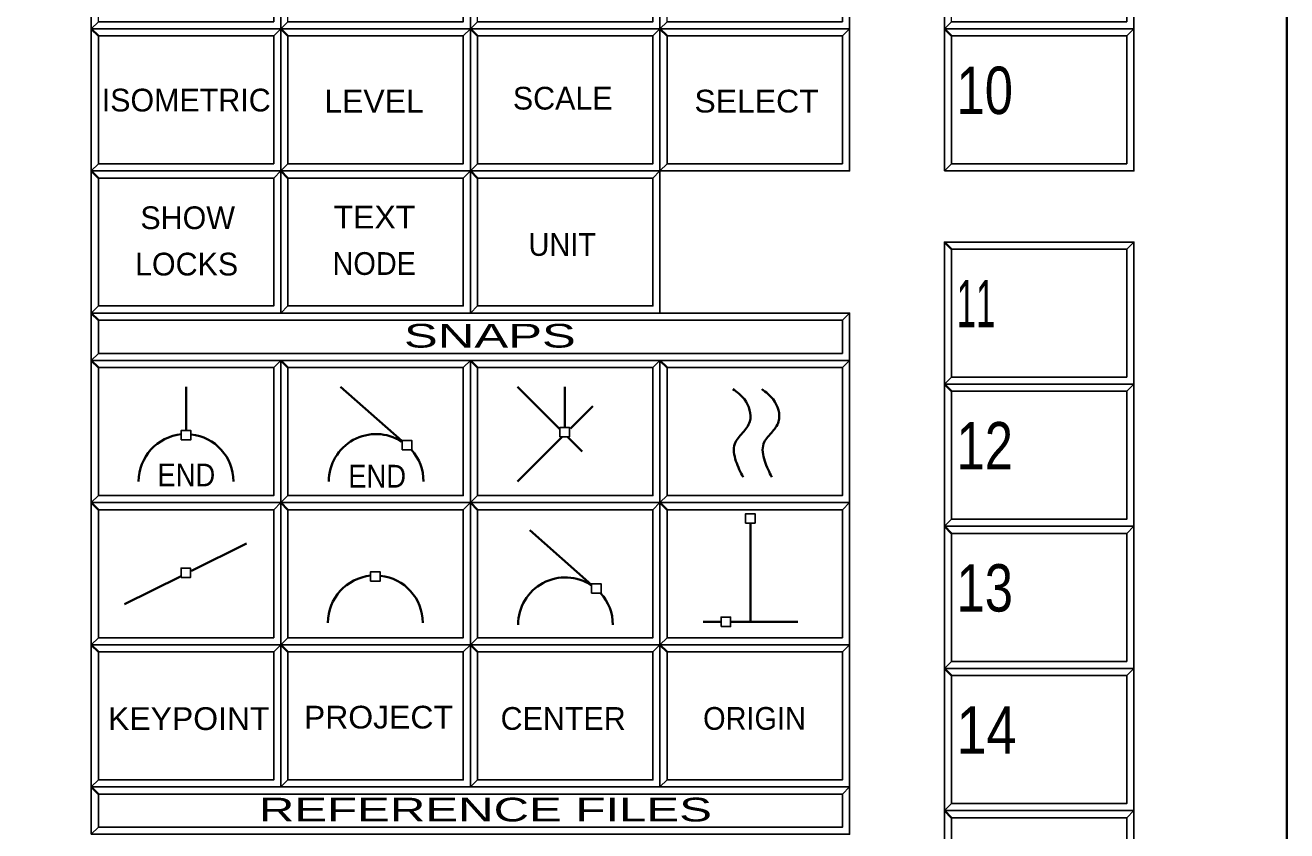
# Model space of a CAD drawing. Extents: x 95906.9 to 95918.9, y 90964.8 to 90972.9.
# Drawn here: x 95916.193 to 95918.855, y 90967.969 to 90969.669 of the extents above; entities that cross this region are included whole.
import ezdxf
from ezdxf.enums import TextEntityAlignment as Align

# ---------------------------------------------------------------- set-up
doc = ezdxf.new("R2010")
doc.units = 0
doc.header["$LTSCALE"] = 0.019
doc.linetypes.add('MEDIUM_DASHED', pattern=[4.5, 3, -1.5])
for name, color, linetype, lineweight in [('1', 7, 'Continuous', 25), ('11', 7, 'Continuous', 25), ('12', 7, 'Continuous', 25), ('2', 7, 'Continuous', 13), ('21', 7, 'Continuous', 25), ('3', 7, 'Continuous', 25), ('4', 7, 'Continuous', 35), ('6', 7, 'Continuous', 35), ('7', 7, 'Continuous', 35)]:
    doc.layers.add(name, color=color, linetype=linetype, lineweight=lineweight)

msp = doc.modelspace()

# ---------------------------------------------------------------- linework, layer by layer
at = {"layer": '1'}
for points in [[(95916.3323, 90969.6617), (95916.7323, 90969.6617), (95916.7323, 90969.9617), (95916.3323, 90969.9617)], [(95916.7323, 90969.6617), (95917.1323, 90969.6617), (95917.1323, 90969.9617), (95916.7323, 90969.9617)], [(95917.1323, 90969.6617), (95917.5323, 90969.6617), (95917.5323, 90969.9617), (95917.1323, 90969.9617)], [(95917.5323, 90969.6617), (95917.9323, 90969.6617), (95917.9323, 90969.9617), (95917.5323, 90969.9617)], [(95918.1323, 90969.6617), (95918.5323, 90969.6617), (95918.5323, 90969.9617), (95918.1323, 90969.9617)], [(95916.3323, 90969.3617), (95916.7323, 90969.3617), (95916.7323, 90969.6617), (95916.3323, 90969.6617)], [(95916.7323, 90969.3617), (95917.1323, 90969.3617), (95917.1323, 90969.6617), (95916.7323, 90969.6617)], [(95917.1323, 90969.3617), (95917.5323, 90969.3617), (95917.5323, 90969.6617), (95917.1323, 90969.6617)], [(95917.5323, 90969.3617), (95917.9323, 90969.3617), (95917.9323, 90969.6617), (95917.5323, 90969.6617)], [(95918.1323, 90969.3617), (95918.5323, 90969.3617), (95918.5323, 90969.6617), (95918.1323, 90969.6617)], [(95916.3323, 90969.0617), (95916.7323, 90969.0617), (95916.7323, 90969.3617), (95916.3323, 90969.3617)], [(95916.7323, 90969.0617), (95917.1323, 90969.0617), (95917.1323, 90969.3617), (95916.7323, 90969.3617)], [(95917.1323, 90969.0617), (95917.5323, 90969.0617), (95917.5323, 90969.3617), (95917.1323, 90969.3617)], [(95918.1323, 90968.9117), (95918.5323, 90968.9117), (95918.5323, 90969.2117), (95918.1323, 90969.2117)], [(95916.3323, 90968.9617), (95917.9323, 90968.9617), (95917.9323, 90969.0617), (95916.3323, 90969.0617)], [(95916.3323, 90968.6617), (95916.7323, 90968.6617), (95916.7323, 90968.9617), (95916.3323, 90968.9617)], [(95916.7323, 90968.6617), (95917.1323, 90968.6617), (95917.1323, 90968.9617), (95916.7323, 90968.9617)], [(95917.1323, 90968.6617), (95917.5323, 90968.6617), (95917.5323, 90968.9617), (95917.1323, 90968.9617)], [(95917.5323, 90968.6617), (95917.9323, 90968.6617), (95917.9323, 90968.9617), (95917.5323, 90968.9617)], [(95918.1323, 90968.6117), (95918.5323, 90968.6117), (95918.5323, 90968.9117), (95918.1323, 90968.9117)], [(95916.3323, 90968.3617), (95916.7323, 90968.3617), (95916.7323, 90968.6617), (95916.3323, 90968.6617)], [(95916.7323, 90968.3617), (95917.1323, 90968.3617), (95917.1323, 90968.6617), (95916.7323, 90968.6617)], [(95917.1323, 90968.3617), (95917.5323, 90968.3617), (95917.5323, 90968.6617), (95917.1323, 90968.6617)], [(95917.5323, 90968.3617), (95917.9323, 90968.3617), (95917.9323, 90968.6617), (95917.5323, 90968.6617)], [(95918.1323, 90968.3117), (95918.5323, 90968.3117), (95918.5323, 90968.6117), (95918.1323, 90968.6117)], [(95916.3323, 90968.0617), (95916.7323, 90968.0617), (95916.7323, 90968.3617), (95916.3323, 90968.3617)], [(95916.7323, 90968.0617), (95917.1323, 90968.0617), (95917.1323, 90968.3617), (95916.7323, 90968.3617)], [(95917.1323, 90968.0617), (95917.5323, 90968.0617), (95917.5323, 90968.3617), (95917.1323, 90968.3617)], [(95917.5323, 90968.0617), (95917.9323, 90968.0617), (95917.9323, 90968.3617), (95917.5323, 90968.3617)], [(95918.1323, 90968.0117), (95918.5323, 90968.0117), (95918.5323, 90968.3117), (95918.1323, 90968.3117)], [(95916.3323, 90967.9617), (95917.9323, 90967.9617), (95917.9323, 90968.0617), (95916.3323, 90968.0617)], [(95918.1323, 90967.7117), (95918.5323, 90967.7117), (95918.5323, 90968.0117), (95918.1323, 90968.0117)]]:
    msp.add_lwpolyline(points, close=True, dxfattribs=at)
at = {"layer": '11'}
for points in [[(95916.3473, 90969.3767), (95916.7173, 90969.3767), (95916.7173, 90969.6467), (95916.3473, 90969.6467)], [(95916.7473, 90969.3767), (95917.1173, 90969.3767), (95917.1173, 90969.6467), (95916.7473, 90969.6467)], [(95917.1473, 90969.3767), (95917.5173, 90969.3767), (95917.5173, 90969.6467), (95917.1473, 90969.6467)], [(95917.5473, 90969.3767), (95917.9173, 90969.3767), (95917.9173, 90969.6467), (95917.5473, 90969.6467)], [(95918.1473, 90969.3767), (95918.5173, 90969.3767), (95918.5173, 90969.6467), (95918.1473, 90969.6467)], [(95916.3473, 90969.0767), (95916.7173, 90969.0767), (95916.7173, 90969.3467), (95916.3473, 90969.3467)], [(95916.7473, 90969.0767), (95917.1173, 90969.0767), (95917.1173, 90969.3467), (95916.7473, 90969.3467)], [(95917.1473, 90969.0767), (95917.5173, 90969.0767), (95917.5173, 90969.3467), (95917.1473, 90969.3467)], [(95918.1473, 90968.9267), (95918.5173, 90968.9267), (95918.5173, 90969.1967), (95918.1473, 90969.1967)], [(95916.3473, 90968.6767), (95916.7173, 90968.6767), (95916.7173, 90968.9467), (95916.3473, 90968.9467)], [(95916.7473, 90968.6767), (95917.1173, 90968.6767), (95917.1173, 90968.9467), (95916.7473, 90968.9467)], [(95917.1473, 90968.6767), (95917.5173, 90968.6767), (95917.5173, 90968.9467), (95917.1473, 90968.9467)], [(95917.5473, 90968.6767), (95917.9173, 90968.6767), (95917.9173, 90968.9467), (95917.5473, 90968.9467)], [(95918.1473, 90968.6267), (95918.5173, 90968.6267), (95918.5173, 90968.8967), (95918.1473, 90968.8967)], [(95916.3473, 90968.3767), (95916.7173, 90968.3767), (95916.7173, 90968.6467), (95916.3473, 90968.6467)], [(95916.7473, 90968.3767), (95917.1173, 90968.3767), (95917.1173, 90968.6467), (95916.7473, 90968.6467)], [(95917.1473, 90968.3767), (95917.5173, 90968.3767), (95917.5173, 90968.6467), (95917.1473, 90968.6467)], [(95917.5473, 90968.3767), (95917.9173, 90968.3767), (95917.9173, 90968.6467), (95917.5473, 90968.6467)], [(95918.1473, 90968.3267), (95918.5173, 90968.3267), (95918.5173, 90968.5967), (95918.1473, 90968.5967)], [(95916.3473, 90968.0767), (95916.7173, 90968.0767), (95916.7173, 90968.3467), (95916.3473, 90968.3467)], [(95916.7473, 90968.0767), (95917.1173, 90968.0767), (95917.1173, 90968.3467), (95916.7473, 90968.3467)], [(95917.1473, 90968.0767), (95917.5173, 90968.0767), (95917.5173, 90968.3467), (95917.1473, 90968.3467)], [(95917.5473, 90968.0767), (95917.9173, 90968.0767), (95917.9173, 90968.3467), (95917.5473, 90968.3467)], [(95918.1473, 90968.0267), (95918.5173, 90968.0267), (95918.5173, 90968.2967), (95918.1473, 90968.2967)], [(95918.1473, 90967.7267), (95918.5173, 90967.7267), (95918.5173, 90967.9967), (95918.1473, 90967.9967)]]:
    msp.add_lwpolyline(points, close=True, dxfattribs=at)
at = {"layer": '12'}
msp.add_lwpolyline([(95916.3473, 90968.6767), (95916.7173, 90968.6767), (95916.7173, 90968.9467), (95916.3473, 90968.9467)], close=True, dxfattribs=at)
at = {"layer": '2'}
for points in [[(95916.3323, 90969.9617), (95916.3323, 90969.6617), (95916.3473, 90969.6767), (95916.3473, 90969.9467), (95916.7173, 90969.9467), (95916.7323, 90969.9617)], [(95916.7323, 90969.9617), (95916.7323, 90969.6617), (95916.7473, 90969.6767), (95916.7473, 90969.9467), (95917.1173, 90969.9467), (95917.1323, 90969.9617)], [(95917.1323, 90969.9617), (95917.1323, 90969.6617), (95917.1473, 90969.6767), (95917.1473, 90969.9467), (95917.5173, 90969.9467), (95917.5323, 90969.9617)], [(95917.5323, 90969.9617), (95917.5323, 90969.6617), (95917.5473, 90969.6767), (95917.5473, 90969.9467), (95917.9173, 90969.9467), (95917.9323, 90969.9617)], [(95918.1323, 90969.9617), (95918.1323, 90969.6617), (95918.1473, 90969.6767), (95918.1473, 90969.9467), (95918.5173, 90969.9467), (95918.5323, 90969.9617)], [(95916.3323, 90969.6617), (95916.3323, 90969.3617), (95916.3473, 90969.3767), (95916.3473, 90969.6467), (95916.7173, 90969.6467), (95916.7323, 90969.6617)], [(95916.7323, 90969.6617), (95916.7323, 90969.3617), (95916.7473, 90969.3767), (95916.7473, 90969.6467), (95917.1173, 90969.6467), (95917.1323, 90969.6617)], [(95917.1323, 90969.6617), (95917.1323, 90969.3617), (95917.1473, 90969.3767), (95917.1473, 90969.6467), (95917.5173, 90969.6467), (95917.5323, 90969.6617)], [(95917.5323, 90969.6617), (95917.5323, 90969.3617), (95917.5473, 90969.3767), (95917.5473, 90969.6467), (95917.9173, 90969.6467), (95917.9323, 90969.6617)], [(95918.1323, 90969.6617), (95918.1323, 90969.3617), (95918.1473, 90969.3767), (95918.1473, 90969.6467), (95918.5173, 90969.6467), (95918.5323, 90969.6617)], [(95916.3323, 90969.3617), (95916.3323, 90969.0617), (95916.3473, 90969.0767), (95916.3473, 90969.3467), (95916.7173, 90969.3467), (95916.7323, 90969.3617)], [(95916.7323, 90969.3617), (95916.7323, 90969.0617), (95916.7473, 90969.0767), (95916.7473, 90969.3467), (95917.1173, 90969.3467), (95917.1323, 90969.3617)], [(95917.1323, 90969.3617), (95917.1323, 90969.0617), (95917.1473, 90969.0767), (95917.1473, 90969.3467), (95917.5173, 90969.3467), (95917.5323, 90969.3617)], [(95918.1323, 90969.2117), (95918.1323, 90968.9117), (95918.1473, 90968.9267), (95918.1473, 90969.1967), (95918.5173, 90969.1967), (95918.5323, 90969.2117)], [(95916.3323, 90969.0617), (95916.3323, 90968.9617), (95916.3473, 90968.9767), (95916.3473, 90969.0467), (95917.9173, 90969.0467), (95917.9323, 90969.0617)], [(95916.3323, 90968.9617), (95916.3323, 90968.6617), (95916.3473, 90968.6767), (95916.3473, 90968.9467), (95916.7173, 90968.9467), (95916.7323, 90968.9617)], [(95916.7323, 90968.9617), (95916.7323, 90968.6617), (95916.7473, 90968.6767), (95916.7473, 90968.9467), (95917.1173, 90968.9467), (95917.1323, 90968.9617)], [(95917.1323, 90968.9617), (95917.1323, 90968.6617), (95917.1473, 90968.6767), (95917.1473, 90968.9467), (95917.5173, 90968.9467), (95917.5323, 90968.9617)], [(95917.5323, 90968.9617), (95917.5323, 90968.6617), (95917.5473, 90968.6767), (95917.5473, 90968.9467), (95917.9173, 90968.9467), (95917.9323, 90968.9617)], [(95918.1323, 90968.9117), (95918.1323, 90968.6117), (95918.1473, 90968.6267), (95918.1473, 90968.8967), (95918.5173, 90968.8967), (95918.5323, 90968.9117)], [(95916.3323, 90968.6617), (95916.3323, 90968.3617), (95916.3473, 90968.3767), (95916.3473, 90968.6467), (95916.7173, 90968.6467), (95916.7323, 90968.6617)], [(95916.7323, 90968.6617), (95916.7323, 90968.3617), (95916.7473, 90968.3767), (95916.7473, 90968.6467), (95917.1173, 90968.6467), (95917.1323, 90968.6617)], [(95917.1323, 90968.6617), (95917.1323, 90968.3617), (95917.1473, 90968.3767), (95917.1473, 90968.6467), (95917.5173, 90968.6467), (95917.5323, 90968.6617)], [(95917.5323, 90968.6617), (95917.5323, 90968.3617), (95917.5473, 90968.3767), (95917.5473, 90968.6467), (95917.9173, 90968.6467), (95917.9323, 90968.6617)], [(95918.1323, 90968.6117), (95918.1323, 90968.3117), (95918.1473, 90968.3267), (95918.1473, 90968.5967), (95918.5173, 90968.5967), (95918.5323, 90968.6117)], [(95916.3323, 90968.3617), (95916.3323, 90968.0617), (95916.3473, 90968.0767), (95916.3473, 90968.3467), (95916.7173, 90968.3467), (95916.7323, 90968.3617)], [(95916.7323, 90968.3617), (95916.7323, 90968.0617), (95916.7473, 90968.0767), (95916.7473, 90968.3467), (95917.1173, 90968.3467), (95917.1323, 90968.3617)], [(95917.1323, 90968.3617), (95917.1323, 90968.0617), (95917.1473, 90968.0767), (95917.1473, 90968.3467), (95917.5173, 90968.3467), (95917.5323, 90968.3617)], [(95917.5323, 90968.3617), (95917.5323, 90968.0617), (95917.5473, 90968.0767), (95917.5473, 90968.3467), (95917.9173, 90968.3467), (95917.9323, 90968.3617)], [(95918.1323, 90968.3117), (95918.1323, 90968.0117), (95918.1473, 90968.0267), (95918.1473, 90968.2967), (95918.5173, 90968.2967), (95918.5323, 90968.3117)], [(95916.3323, 90968.0617), (95916.3323, 90967.9617), (95916.3473, 90967.9767), (95916.3473, 90968.0467), (95917.9173, 90968.0467), (95917.9323, 90968.0617)], [(95918.1323, 90968.0117), (95918.1323, 90967.7117), (95918.1473, 90967.7267), (95918.1473, 90967.9967), (95918.5173, 90967.9967), (95918.5323, 90968.0117)]]:
    msp.add_lwpolyline(points, close=True, dxfattribs=at)
at = {"layer": '21'}
for points in [[(95916.3473, 90968.9767), (95917.9173, 90968.9767), (95917.9173, 90969.0467), (95916.3473, 90969.0467)], [(95916.3473, 90967.9767), (95917.9173, 90967.9767), (95917.9173, 90968.0467), (95916.3473, 90968.0467)]]:
    msp.add_lwpolyline(points, close=True, dxfattribs=at)
at = {"layer": '3'}
for points in [[(95916.3323, 90969.6617), (95916.7323, 90969.6617), (95916.7323, 90969.9617), (95916.7173, 90969.9467), (95916.7173, 90969.6767), (95916.3473, 90969.6767)], [(95916.7323, 90969.6617), (95917.1323, 90969.6617), (95917.1323, 90969.9617), (95917.1173, 90969.9467), (95917.1173, 90969.6767), (95916.7473, 90969.6767)], [(95917.1323, 90969.6617), (95917.5323, 90969.6617), (95917.5323, 90969.9617), (95917.5173, 90969.9467), (95917.5173, 90969.6767), (95917.1473, 90969.6767)], [(95917.5323, 90969.6617), (95917.9323, 90969.6617), (95917.9323, 90969.9617), (95917.9173, 90969.9467), (95917.9173, 90969.6767), (95917.5473, 90969.6767)], [(95918.1323, 90969.6617), (95918.5323, 90969.6617), (95918.5323, 90969.9617), (95918.5173, 90969.9467), (95918.5173, 90969.6767), (95918.1473, 90969.6767)], [(95916.3323, 90969.3617), (95916.7323, 90969.3617), (95916.7323, 90969.6617), (95916.7173, 90969.6467), (95916.7173, 90969.3767), (95916.3473, 90969.3767)], [(95916.7323, 90969.3617), (95917.1323, 90969.3617), (95917.1323, 90969.6617), (95917.1173, 90969.6467), (95917.1173, 90969.3767), (95916.7473, 90969.3767)], [(95917.1323, 90969.3617), (95917.5323, 90969.3617), (95917.5323, 90969.6617), (95917.5173, 90969.6467), (95917.5173, 90969.3767), (95917.1473, 90969.3767)], [(95917.5323, 90969.3617), (95917.9323, 90969.3617), (95917.9323, 90969.6617), (95917.9173, 90969.6467), (95917.9173, 90969.3767), (95917.5473, 90969.3767)], [(95918.1323, 90969.3617), (95918.5323, 90969.3617), (95918.5323, 90969.6617), (95918.5173, 90969.6467), (95918.5173, 90969.3767), (95918.1473, 90969.3767)], [(95916.3323, 90969.0617), (95916.7323, 90969.0617), (95916.7323, 90969.3617), (95916.7173, 90969.3467), (95916.7173, 90969.0767), (95916.3473, 90969.0767)], [(95916.7323, 90969.0617), (95917.1323, 90969.0617), (95917.1323, 90969.3617), (95917.1173, 90969.3467), (95917.1173, 90969.0767), (95916.7473, 90969.0767)], [(95917.1323, 90969.0617), (95917.5323, 90969.0617), (95917.5323, 90969.3617), (95917.5173, 90969.3467), (95917.5173, 90969.0767), (95917.1473, 90969.0767)], [(95918.1323, 90968.9117), (95918.5323, 90968.9117), (95918.5323, 90969.2117), (95918.5173, 90969.1967), (95918.5173, 90968.9267), (95918.1473, 90968.9267)], [(95916.3323, 90968.9617), (95917.9323, 90968.9617), (95917.9323, 90969.0617), (95917.9173, 90969.0467), (95917.9173, 90968.9767), (95916.3473, 90968.9767)], [(95916.3323, 90968.6617), (95916.7323, 90968.6617), (95916.7323, 90968.9617), (95916.7173, 90968.9467), (95916.7173, 90968.6767), (95916.3473, 90968.6767)], [(95916.7323, 90968.6617), (95917.1323, 90968.6617), (95917.1323, 90968.9617), (95917.1173, 90968.9467), (95917.1173, 90968.6767), (95916.7473, 90968.6767)], [(95917.1323, 90968.6617), (95917.5323, 90968.6617), (95917.5323, 90968.9617), (95917.5173, 90968.9467), (95917.5173, 90968.6767), (95917.1473, 90968.6767)], [(95917.5323, 90968.6617), (95917.9323, 90968.6617), (95917.9323, 90968.9617), (95917.9173, 90968.9467), (95917.9173, 90968.6767), (95917.5473, 90968.6767)], [(95918.1323, 90968.6117), (95918.5323, 90968.6117), (95918.5323, 90968.9117), (95918.5173, 90968.8967), (95918.5173, 90968.6267), (95918.1473, 90968.6267)], [(95916.3323, 90968.3617), (95916.7323, 90968.3617), (95916.7323, 90968.6617), (95916.7173, 90968.6467), (95916.7173, 90968.3767), (95916.3473, 90968.3767)], [(95916.7323, 90968.3617), (95917.1323, 90968.3617), (95917.1323, 90968.6617), (95917.1173, 90968.6467), (95917.1173, 90968.3767), (95916.7473, 90968.3767)], [(95917.1323, 90968.3617), (95917.5323, 90968.3617), (95917.5323, 90968.6617), (95917.5173, 90968.6467), (95917.5173, 90968.3767), (95917.1473, 90968.3767)], [(95917.5323, 90968.3617), (95917.9323, 90968.3617), (95917.9323, 90968.6617), (95917.9173, 90968.6467), (95917.9173, 90968.3767), (95917.5473, 90968.3767)], [(95918.1323, 90968.3117), (95918.5323, 90968.3117), (95918.5323, 90968.6117), (95918.5173, 90968.5967), (95918.5173, 90968.3267), (95918.1473, 90968.3267)], [(95916.3323, 90968.0617), (95916.7323, 90968.0617), (95916.7323, 90968.3617), (95916.7173, 90968.3467), (95916.7173, 90968.0767), (95916.3473, 90968.0767)], [(95916.7323, 90968.0617), (95917.1323, 90968.0617), (95917.1323, 90968.3617), (95917.1173, 90968.3467), (95917.1173, 90968.0767), (95916.7473, 90968.0767)], [(95917.1323, 90968.0617), (95917.5323, 90968.0617), (95917.5323, 90968.3617), (95917.5173, 90968.3467), (95917.5173, 90968.0767), (95917.1473, 90968.0767)], [(95917.5323, 90968.0617), (95917.9323, 90968.0617), (95917.9323, 90968.3617), (95917.9173, 90968.3467), (95917.9173, 90968.0767), (95917.5473, 90968.0767)], [(95918.1323, 90968.0117), (95918.5323, 90968.0117), (95918.5323, 90968.3117), (95918.5173, 90968.2967), (95918.5173, 90968.0267), (95918.1473, 90968.0267)], [(95916.3323, 90967.9617), (95917.9323, 90967.9617), (95917.9323, 90968.0617), (95917.9173, 90968.0467), (95917.9173, 90967.9767), (95916.3473, 90967.9767)], [(95918.1323, 90967.7117), (95918.5323, 90967.7117), (95918.5323, 90968.0117), (95918.5173, 90967.9967), (95918.5173, 90967.7267), (95918.1473, 90967.7267)]]:
    msp.add_lwpolyline(points, close=True, dxfattribs=at)
at = {"layer": '4'}
for p, q in [((95916.3473, 90969.6467), (95916.3323, 90969.6617)), ((95916.7473, 90969.6467), (95916.7323, 90969.6617)), ((95917.1473, 90969.6467), (95917.1323, 90969.6617)), ((95917.5473, 90969.6467), (95917.5323, 90969.6617)), ((95918.1473, 90969.6467), (95918.1323, 90969.6617)), ((95916.3473, 90969.3467), (95916.3323, 90969.3617)), ((95916.7473, 90969.3467), (95916.7323, 90969.3617)), ((95917.1473, 90969.3467), (95917.1323, 90969.3617)), ((95918.1473, 90969.1967), (95918.1323, 90969.2117)), ((95916.3473, 90969.0467), (95916.3323, 90969.0617)), ((95916.3473, 90968.9467), (95916.3323, 90968.9617)), ((95916.7473, 90968.9467), (95916.7323, 90968.9617)), ((95917.1473, 90968.9467), (95917.1323, 90968.9617)), ((95917.5473, 90968.9467), (95917.5323, 90968.9617)), ((95918.1473, 90968.8967), (95918.1323, 90968.9117)), ((95916.3473, 90968.6467), (95916.3323, 90968.6617)), ((95916.7473, 90968.6467), (95916.7323, 90968.6617)), ((95917.1473, 90968.6467), (95917.1323, 90968.6617)), ((95917.5473, 90968.6467), (95917.5323, 90968.6617)), ((95918.1473, 90968.5967), (95918.1323, 90968.6117)), ((95916.3473, 90968.3467), (95916.3323, 90968.3617)), ((95916.7473, 90968.3467), (95916.7323, 90968.3617)), ((95917.1473, 90968.3467), (95917.1323, 90968.3617)), ((95917.5473, 90968.3467), (95917.5323, 90968.3617)), ((95918.1473, 90968.2967), (95918.1323, 90968.3117)), ((95916.3473, 90968.0467), (95916.3323, 90968.0617)), ((95918.1473, 90967.9967), (95918.1323, 90968.0117))]:
    msp.add_line(p, q, dxfattribs=at)
at = {"layer": '6'}
for p, q in [((95916.5323, 90968.9064), (95916.5323, 90968.814)), ((95916.9875, 90968.7918), (95916.8584, 90968.9064)), ((95917.2316, 90968.9063), (95917.3204, 90968.8175)), ((95917.3316, 90968.8205), (95917.3316, 90968.9063)), ((95917.2316, 90968.7063), (95917.3252, 90968.7999)), ((95917.7231, 90968.4099), (95917.7231, 90968.6184)), ((95917.3879, 90968.4885), (95917.2578, 90968.6039)), ((95916.6596, 90968.5756), (95916.5441, 90968.5178)), ((95916.4027, 90968.4471), (95916.5207, 90968.506)), ((95917.6231, 90968.4099), (95917.6595, 90968.4099)), ((95917.8231, 90968.4099), (95917.6814, 90968.4099))]:
    msp.add_line(p, q, dxfattribs=at)
at = {"layer": '6', "linetype": 'MEDIUM_DASHED'}
for p, q in [((95917.3908, 90968.8655), (95917.3436, 90968.8183)), ((95917.3682, 90968.7696), (95917.3374, 90968.8003))]:
    msp.add_line(p, q, dxfattribs=at)
at = {"layer": '6', "lineweight": 25}
for points in [[(95916.5223, 90968.794), (95916.5423, 90968.794), (95916.5423, 90968.814), (95916.5223, 90968.814)], [(95917.3213, 90968.8005), (95917.3413, 90968.8005), (95917.3413, 90968.8205), (95917.3213, 90968.8205)], [(95916.9886, 90968.7731), (95917.0086, 90968.7731), (95917.0086, 90968.7931), (95916.9886, 90968.7931)], [(95917.7131, 90968.6184), (95917.7331, 90968.6184), (95917.7331, 90968.6384), (95917.7131, 90968.6384)], [(95916.5217, 90968.5034), (95916.5417, 90968.5034), (95916.5417, 90968.5234), (95916.5217, 90968.5234)], [(95916.9218, 90968.4957), (95916.9418, 90968.4957), (95916.9418, 90968.5157), (95916.9218, 90968.5157)], [(95917.388, 90968.4706), (95917.408, 90968.4706), (95917.408, 90968.4906), (95917.388, 90968.4906)], [(95917.6614, 90968.4001), (95917.6814, 90968.4001), (95917.6814, 90968.4201), (95917.6614, 90968.4201)]]:
    msp.add_lwpolyline(points, close=True, dxfattribs=at)
at = {"layer": '6'}
for centre, start, end in [((95916.5323, 90968.7064), 95.4769, 180), ((95916.5323, 90968.7064), 0, 83.8749), ((95916.9334, 90968.7064), 57.6387, 180), ((95916.9334, 90968.7064), 0, 41.8322), ((95916.9318, 90968.4081), 95.6733, 180), ((95916.9318, 90968.4081), 95.3189, 95.3388), ((95916.9318, 90968.4081), 0, 83.9551), ((95917.3328, 90968.4039), 56.474, 180), ((95917.3328, 90968.4039), 0, 41.9755)]:
    msp.add_arc(centre, 0.1, start, end, dxfattribs=at)
for points in [[(95917.7079, 90968.7153), (95917.6927, 90968.7495), (95917.6902, 90968.7861), (95917.7066, 90968.8089), (95917.7218, 90968.8329), (95917.7104, 90968.8798), (95917.6863, 90968.9012)], [(95917.7686, 90968.7153), (95917.7534, 90968.7495), (95917.7509, 90968.7861), (95917.7673, 90968.8089), (95917.7825, 90968.8329), (95917.7711, 90968.8798), (95917.7471, 90968.9012)]]:
    msp.add_spline(points, degree=3, dxfattribs=at)
at = {"layer": '7'}
msp.add_lwpolyline([(95906.8548, 90972.8617), (95918.8548, 90972.8617), (95918.8548, 90964.7617), (95906.8548, 90964.7617)], close=True, dxfattribs=at)

# ---------------------------------------------------------------- texts
at = {"layer": '6'}
for s, width, p in [('10', 0.8, (95918.1581, 90969.4818)), ('11', 0.55, (95918.1581, 90969.0318)), ('12', 0.8, (95918.1581, 90968.7318)), ('13', 0.8, (95918.1581, 90968.4318)), ('14', 0.85, (95918.1581, 90968.1318))]:
    msp.add_text(s, height=0.1, dxfattribs=dict(at, width=width)).set_placement(p)
for s, p in [('ISOMETRIC', (95916.5327, 90969.4872)), ('SCALE', (95917.3271, 90969.4912)), ('SHOW', (95916.5358, 90969.2389)), ('LOCKS', (95916.5335, 90969.1411)), ('CENTER', (95917.328, 90968.1822))]:
    msp.add_text(s, height=0.048, dxfattribs=at).set_placement(p, align=Align.CENTER)
for s, width, p in [('LEVEL', 1.05, (95916.929, 90969.4849)), ('SELECT', 1.05, (95917.7361, 90969.485)), ('TEXT', 1.05, (95916.9298, 90969.2403)), ('UNIT', 0.95, (95917.3261, 90969.1825)), ('NODE', 0.95, (95916.9294, 90969.1423)), ('END', 0.9, (95916.5329, 90968.6961)), ('END', 0.9, (95916.9356, 90968.6935)), ('KEYPOINT', 1.05, (95916.5381, 90968.1819)), ('PROJECT', 1.05, (95916.9383, 90968.185)), ('ORIGIN', 0.95, (95917.7317, 90968.1823))]:
    msp.add_text(s, height=0.048, dxfattribs=dict(at, width=width)).set_placement(p, align=Align.CENTER)
at = {"layer": '7'}
for s, width, p in [('         SNAPS         ', 1.6, (95917.1734, 90968.9889)), ('         REFERENCE FILES         ', 1.55, (95917.164, 90967.9889))]:
    msp.add_text(s, height=0.05, dxfattribs=dict(at, width=width)).set_placement(p, align=Align.CENTER)

doc.saveas('drawing.dxf')
